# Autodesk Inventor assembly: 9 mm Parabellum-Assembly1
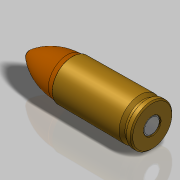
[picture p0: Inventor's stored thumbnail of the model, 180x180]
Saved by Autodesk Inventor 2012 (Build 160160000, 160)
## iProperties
Company: MH Vaaben Teknik
Created: 2011-12
Part Number: 9 mm Parabellum-Assembly1
Document SubType Name: Assembly
Designer: Michael Høgh
Project: Sten MK II
Material: Copper
Mass: 2.86854 g
Surface Area: 13.1439 cm^2
Volume: 0.339174 cm^3
Density: 8.45744 g/cm^3
Author: Michael Høgh
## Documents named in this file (4)
- C:\Users\Michael Høgh\Dropbox\Documents\TEC-Ballerup\I - Inventor\2011\Ideer\Sten MK II\Assemblies\9 mm Parabellum-Assembly1.iam
- C:\Users\Michael Høgh\Dropbox\Documents\TEC-Ballerup\I - Inventor\2011\Ideer\Sten MK II\Components\9 mm Parabellum Cartridge Case.ipt
- C:\Users\Michael Høgh\Dropbox\Documents\TEC-Ballerup\I - Inventor\2011\Ideer\Sten MK II\Components\Firering Cap.ipt
- C:\Users\Michael Høgh\Dropbox\Documents\TEC-Ballerup\I - Inventor\2011\Ideer\Sten MK II\Components\9 mm Parabellum Projectile.ipt
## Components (3 placed, 3 different names)
1. 9 mm Parabellum Cartridge Case:1 — Mate:1, Mate:2, Mate:3, Flush:1
2. Firering Cap:1 — Mate:1, Mate:2
3. 9 mm Parabellum Projectile:1 — Mate:3, Flush:1
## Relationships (4: Mate 3, Flush 1)
- Mate:1: 9 mm Parabellum Cartridge Case:1 ↔ Firering Cap:1
- Mate:2: 9 mm Parabellum Cartridge Case:1 ↔ Firering Cap:1
- Mate:3: 9 mm Parabellum Cartridge Case:1 ↔ 9 mm Parabellum Projectile:1
- Flush:1: 9 mm Parabellum Cartridge Case:1 ↔ 9 mm Parabellum Projectile:1
